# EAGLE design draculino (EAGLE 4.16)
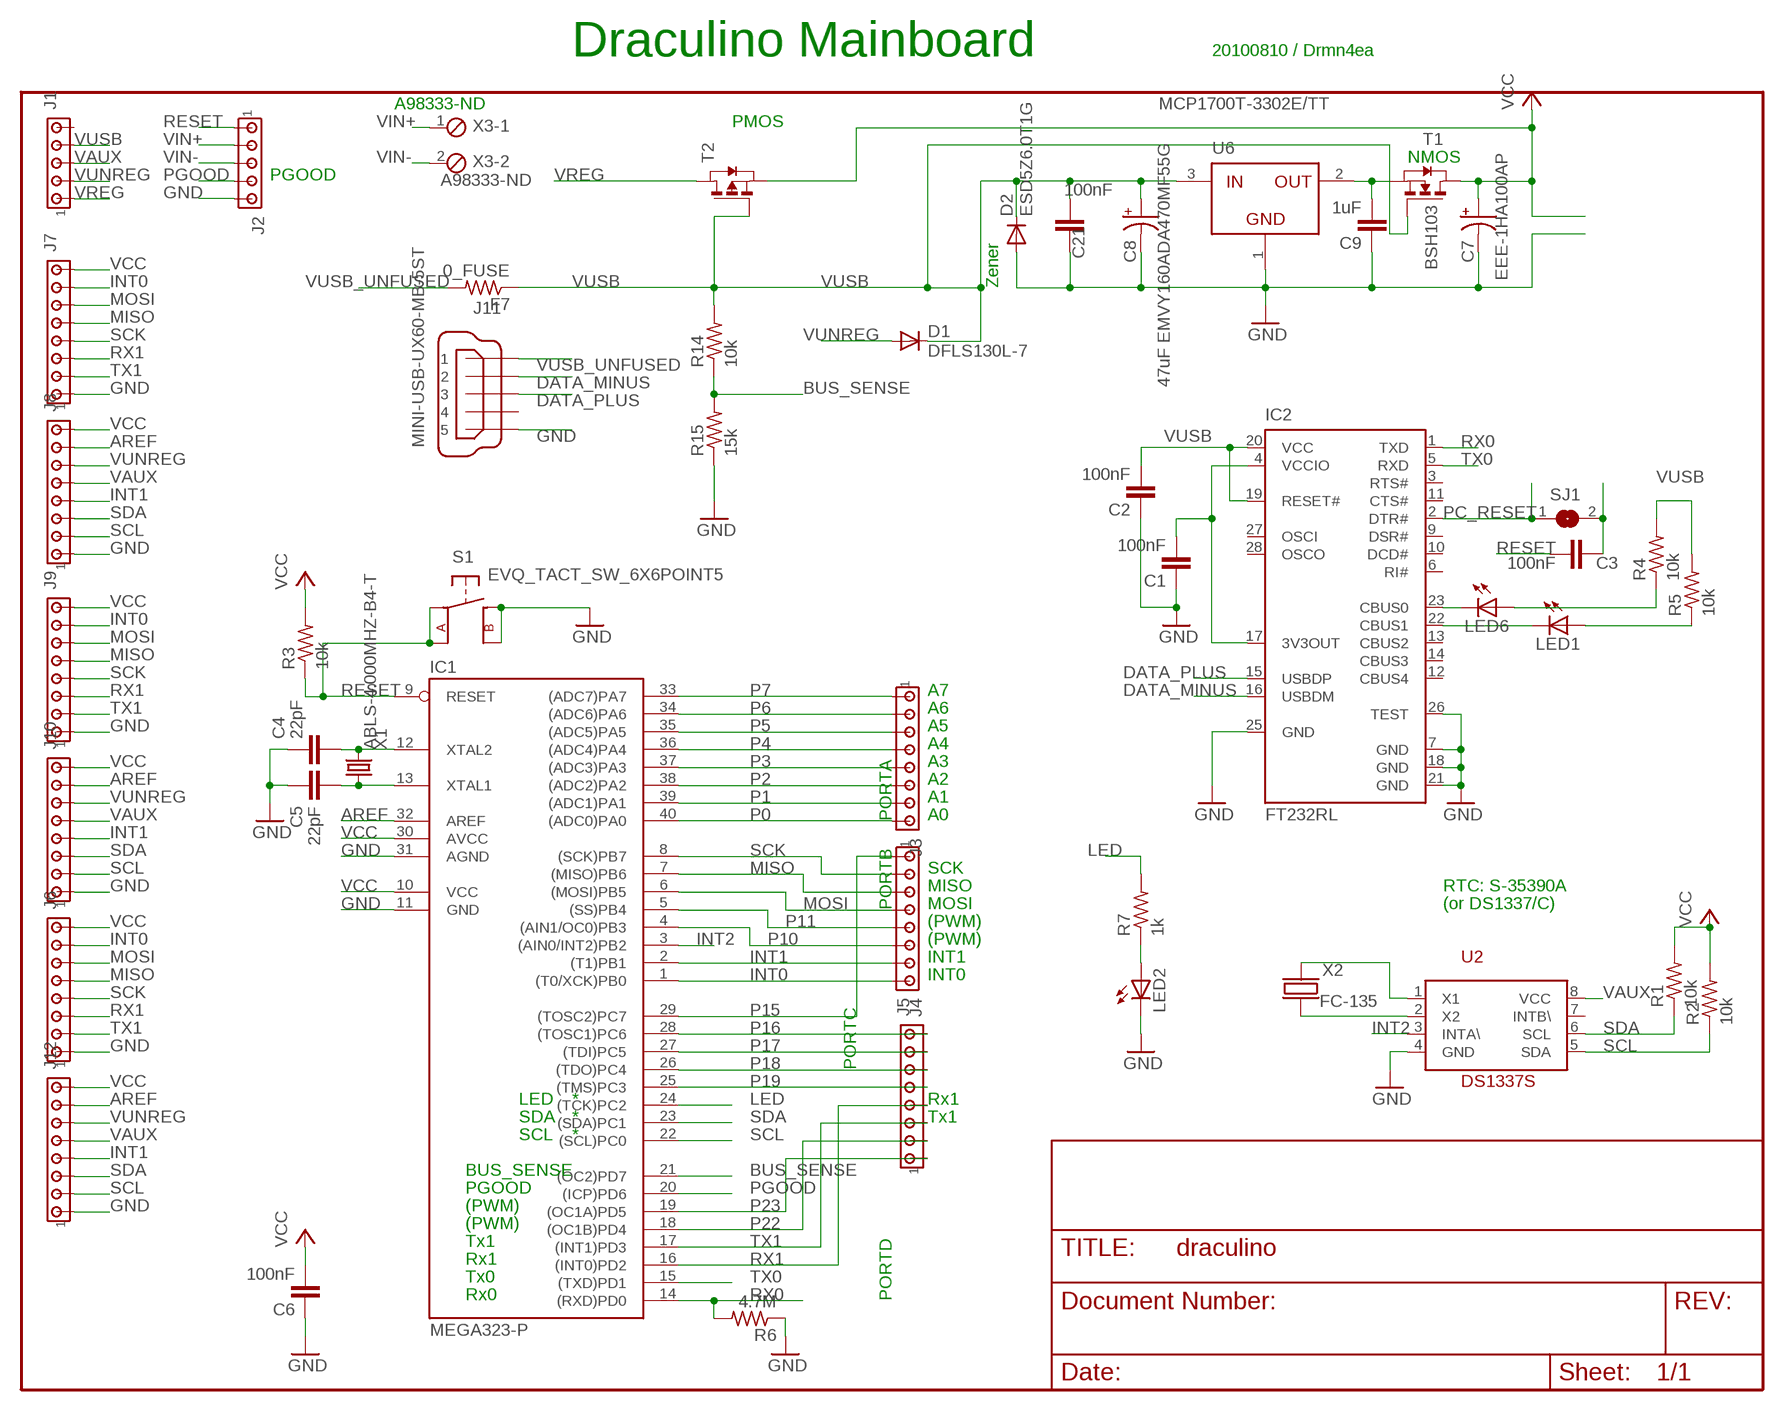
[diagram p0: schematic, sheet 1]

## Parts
C1  100nF  C-EUC0805K  [C0805K]
C2  100nF  C-EUC0805K  [C0805K]
C3  100nF  C-EUC0805K  [C0805K]
C4  22pF  C-EUC0805K  [C0805K]
C5  22pF  C-EUC0805K  [C0805K]
C6  100nF  C-EUC0805K  [C0805K]
C7  EEE-1HA100AP  CPOL-USD  [PANASONIC_D]
C8  47uF EMVY160ADA470MF55G  CPOL-USD  [PANASONIC_D]
C9  1uF  C-EUC0805K  [C0805K]
C21  100nF  C-EUC0805K  [C0805K]
D1  DFLS130L-7  DIODE-SOD123  [SOD123]
D2  ESD5Z6.0T1G  DIODE-SOD123  [SOD123]
F7  0_FUSE  R-US_R0603  [R0603]
IC1  MEGA323-P  [DIL40]
IC2  FT232RL  [SSOP28]
J1  MTA05-100  [10X05MTA]
J2  MTA05-100  [10X05MTA]
J3  MTA08-100  [10X08MTA]
J4  MTA08-100  [10X08MTA]
J5  MTA08-100  [10X08MTA]
J6  MTA08-100  [10X08MTA]
J7  MTA08-100  [10X08MTA]
J8  MTA08-100  [10X08MTA]
J9  MTA08-100  [10X08MTA]
J10  MTA08-100  [10X08MTA]
J11  MINI-USB-UX60-MB-5ST  [UX60-MB-5ST]
J12  MTA08-100  [10X08MTA]
LED1  LEDCHIP-LED0805  [CHIP-LED0805]
LED2  LEDCHIP-LED0805  [CHIP-LED0805]
LED6  LEDCHIP-LED0805  [CHIP-LED0805]
R1  10k  R-US_R0805  [R0805]
R2  10k  R-US_R0805  [R0805]
R3  10k  R-US_R0805  [R0805]
R4  10k  R-US_R0805  [R0805]
R5  10k  R-US_R0805  [R0805]
R6  4.7M  R-US_R0805  [R0805]
R7  1k  R-US_R0805  [R0805]
R14  10k  R-US_R0805  [R0805]
R15  15k  R-US_R0805  [R0805]
S1  EVQ_TACT_SW_6X6POINT5  [EVQ_TACT_SW_6X6POINT5]
SJ1  SJ  [SJ]
T1  BSH103  NMOSSOT23  [SOT-23]
T2  PMOSSOT23  [SOT-23]
U2  DS1337S  [SO-8]
U6  MCP1700T-3302E/TT  MCP1700T  [SOT23]
X1  ABLS-4.000MHZ-B4-T  CRYSTALSM49  [SM49]
X2  FC-135  [FC-135]
X3  A98333-ND  MPT2  [2POL254]

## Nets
AREF: IC1.32(AREF) J8.7 J10.7 J12.7
BUS_SENSE: IC1.21((OC2)PD7) R14.1 R15.2
DATA_MINUS: IC2.16(USBDM) J11.2
DATA_PLUS: IC2.15(USBDP) J11.3
GND: C1.1 C2.1 C4.2 C5.1 C6.1 C7.- C8.- C9.1 C21.1 D2.A IC1.11(GND) IC1.31(AGND) IC2.7(GND) IC2.18(GND) IC2.21(GND) IC2.25(GND) IC2.26(TEST) J2.5 J6.1 J7.1 J8.1 J9.1 J10.1 J11.5 J12.1 LED2.C R6.1 R15.1 S1.B S1.B2(B1) U2.4(GND) U6.1(GND)
INT0: IC1.1((T0/XCK)PB0) J4.8 J6.7 J7.7 J9.7
INT1: IC1.2((T1)PB1) J4.7 J8.4 J10.4 J12.4
INT2: IC1.3((AIN0/INT2)PB2) U2.3(INTA\)
LED: IC1.24((TCK)PC2) R7.2
MISO: IC1.7((MISO)PB6) J4.3 J6.5 J7.5 J9.5
MOSI: IC1.6((MOSI)PB5) J4.4 J6.6 J7.6 J9.6
N$1: C3.1 SJ1.2
N$2: C4.1 IC1.12(XTAL2) X1.2
N$3: LED2.A R7.1
N$4: IC2.22(CBUS1) LED1.C
N$5: C5.2 IC1.13(XTAL1) X1.1
N$6: U2.2(X2) X2.P$2(X2)
N$7: C9.2 T1.2(S) U6.2(OUT)
N$8: U2.1(X1) X2.P$1(X1)
N$9: C1.2 IC2.4(VCCIO) IC2.17(3V3OUT)
N$10: LED6.A R4.1
N$13: IC2.23(CBUS0) LED6.C
N$14: LED1.A R5.1
P0: IC1.40((ADC0)PA0) J3.8
P1: IC1.39((ADC1)PA1) J3.7
P2: IC1.38((ADC2)PA2) J3.6
P3: IC1.37((ADC3)PA3) J3.5
P4: IC1.36((ADC4)PA4) J3.4
P5: IC1.35((ADC5)PA5) J3.3
P6: IC1.34((ADC6)PA6) J3.2
P7: IC1.33((ADC7)PA7) J3.1
P10: IC1.4((AIN1/OC0)PB3) J4.6
P11: IC1.5((SS)PB4) J4.5
P15: IC1.29((TOSC2)PC7) J4.1
P16: IC1.28((TOSC1)PC6) J5.8
P17: IC1.27((TDI)PC5) J5.7
P18: IC1.26((TDO)PC4) J5.6
P19: IC1.25((TMS)PC3) J5.5
P22: IC1.18((OC1B)PD4) J5.2
P23: IC1.19((OC1A)PD5) J5.1
PC_RESET: IC2.2(DTR#) SJ1.1
PGOOD: IC1.20((ICP)PD6) J2.4
RESET: C3.2 IC1.9(RESET) J2.1 R3.1 S1.A S1.A2(A1)
RX0: IC1.14((RXD)PD0) IC2.1(TXD) R6.2
RX1: IC1.16((INT0)PD2) J5.4 J6.3 J7.3 J9.3
SCK: IC1.8((SCK)PB7) J4.2 J6.4 J7.4 J9.4
SCL: IC1.22((SCL)PC0) J8.2 J10.2 J12.2 R2.1 U2.5(SDA)
SDA: IC1.23((SDA)PC1) J8.3 J10.3 J12.3 R1.1 U2.6(SCL)
TX0: IC1.15((TXD)PD1) IC2.5(RXD)
TX1: IC1.17((INT1)PD3) J5.3 J6.2 J7.2 J9.2
VAUX: J1.3 J8.5 J10.5 J12.5 U2.8(VCC)
VCC: C6.2 C7.+ IC1.10(VCC) IC1.30(AVCC) J6.8 J7.8 J8.8 J9.8 J10.8 J12.8 R1.2 R2.2 R3.2 T1.1(D) T2.2(S)
VIN+: J2.2 X3.1
VIN-: J2.3 X3.2
VREG: J1.1 T2.1(D)
VUNREG: D1.A J1.2 J8.6 J10.6 J12.6
VUSB: C2.2 C8.+ C21.2 D1.C D2.C F7.1 IC2.19(RESET#) IC2.20(VCC) J1.4 R4.2 R5.2 R14.2 T1.3(G) T2.3(G) U6.3(IN)
VUSB_UNFUSED: F7.2 J11.1
Unconnected: IC2.3(RTS#) IC2.6(RI#) IC2.9(DSR#) IC2.10(DCD#) IC2.11(CTS#) IC2.12(CBUS4) IC2.13(CBUS2) IC2.14(CBUS3) IC2.27(OSCI) IC2.28(OSCO) J1.5 J11.4 U2.7(INTB\)

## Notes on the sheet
- Draculino Mainboard | 20100810 / Drmn4ea
- A98333-ND
- PMOS
- NMOS
- PGOOD
- Zener
- A7
- A6
- A5
- A4
- A3
- A2
- A1
- PORTA | A0
- SCK
- MISO | RTC: S-35390A
- PORTB | MOSI | (or DS1337/C)
- (PWM)
- (PWM)
- INT1
- INT0
- PORTC
- LED | * | Rx1
- SDA | * | Tx1
- SCL | *
- BUS_SENSE
- PGOOD
- (PWM)
- (PWM)
- Tx1
- Rx1
- Tx0
- Rx0 | PORTD

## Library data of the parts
C1-C6 C9 C21 = rcl:C-EU: CAPACITOR, European symbol
C7 C8 = rcl:CPOL-US: POLARIZED CAPACITOR, American symbol
D1 D2 = diode:DIODE-: DIODE
F7 R1-R7 R14 R15 = rcl:R-US_: RESISTOR, American symbol
IC1 = avr-4:MEGA323-P: MICROCONTROLLER 32 Kbytes FLASH 2 Kbytes SRAM 1 Kbytes EEPROM USART 8-channel 10 bit ADC
IC2 = ftdichip:FT232R: Source: http://www.ftdichip.com/Documents/DataSheets/DS_FT232R_v104.pdf
J1 J2 = con-amp:MTA05-100: AMP connector
J3-J10 J12 = con-amp:MTA08-100: AMP connector
J11 = con-hirose:MINI-USB-: MINI USB Connector Source: http://www.hirose.co.jp/cataloge_hp/e24000019.pdf
LED1 LED2 LED6 = led:LED: LED
S1 = tim:EVQ_TACT_SW_6X6POINT5: Panasonic EVQ series 6.5x6.0mm SMD tactile switch. 20100114 / tgipson
SJ1 = jumper:SJ: SMD solder JUMPER
T1 = zetex:NMOSSOT23: MOS FET
T2 = zetex:PMOSSOT23: MOS FET
U2 = tim:DS1337
U6 = mideeval:MCP1700T: Voltage regulator in SOT23. 20060228 / tgipson
X1 = crystal:CRYSTAL: CRYSTAL
X2 = tim:FC-135
X3 = con-phoenix-254:MPT2: PHOENIX CONNECTOR

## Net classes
1 pwr: width 0.305 mm, drill 0.203 mm, clearance 0.508 mm
4 digital: width 0.203 mm, drill 0.203 mm, clearance 0.381 mm

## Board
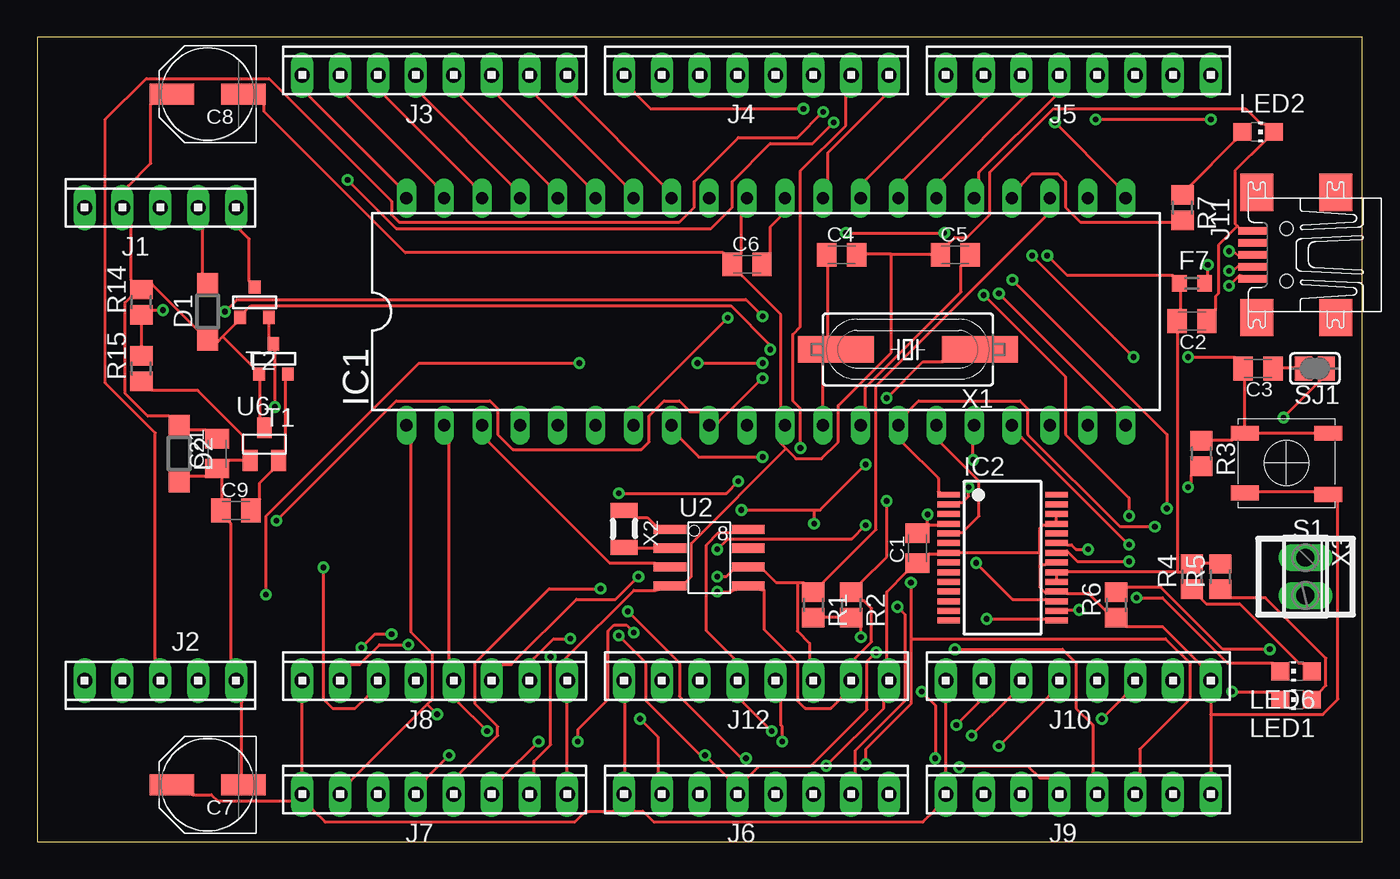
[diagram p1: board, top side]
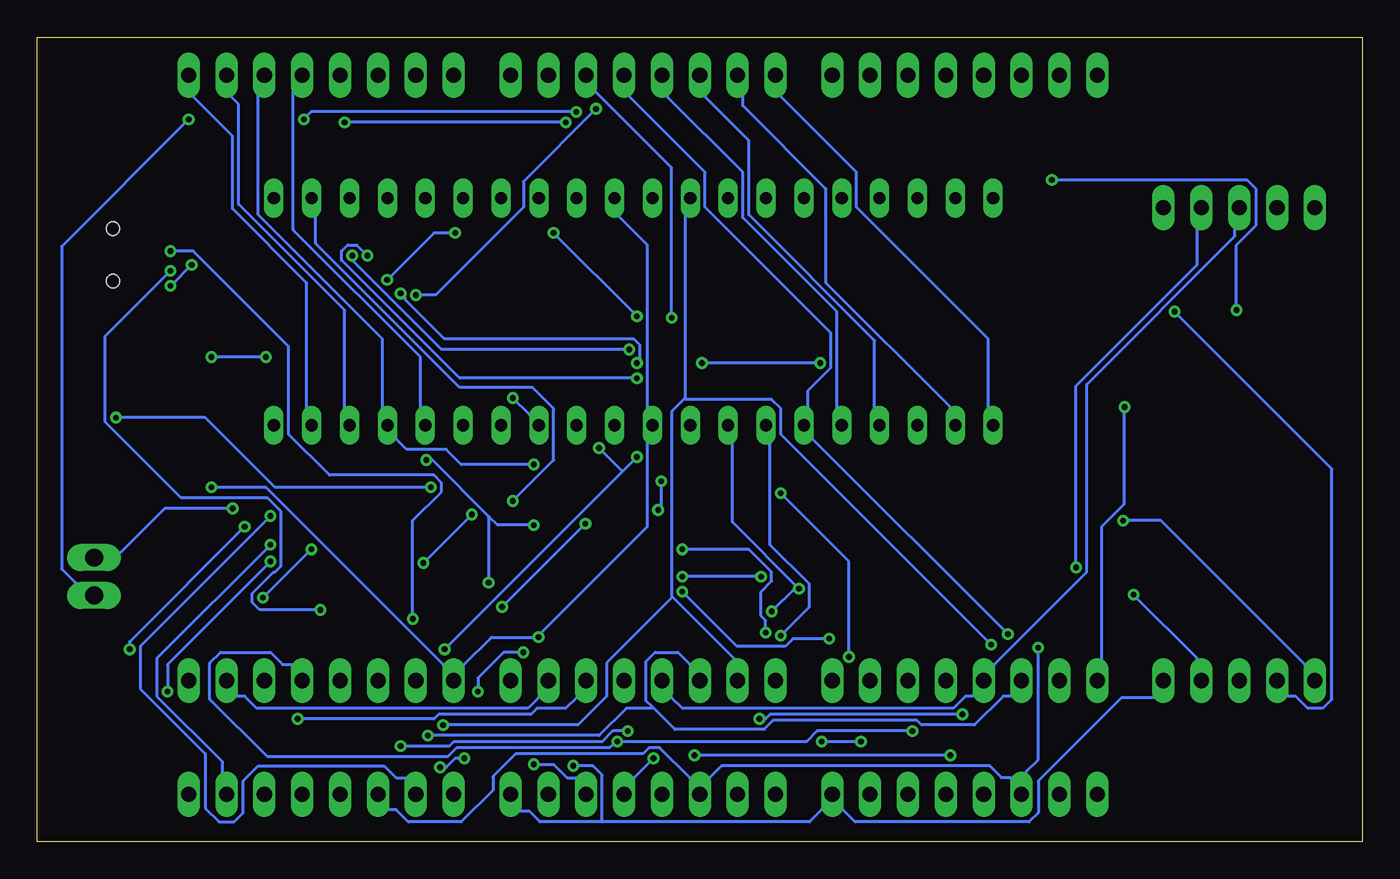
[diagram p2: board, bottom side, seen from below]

Size 88.9 x 53.98 mm. Coordinates in mm from the lower left corner, seen from the top.
Outline: 0,0 88.9,0 88.9,53.98 0,53.98 0,0
Copper layers (1*16): Top 0.035mm / dielectric 1.5mm / Bottom 0.035mm
Design rules "default": minimum track width 8mil, minimum drill 15mil, track to track 8mil, track to pad 8mil, pad to pad 8mil, via to via 8mil, smd to smd 8mil, copper to edge 40mil, drill to drill 8mil, minimum pad ring 10mil, minimum via ring 8mil, stop-mask expansion 4mil, vias tented up to drill 0mil, thermal gap 10mil

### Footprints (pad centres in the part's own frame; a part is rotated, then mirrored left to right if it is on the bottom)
C0805K = smd 1.3 x 1.6: 1 -1,0; 2 1,0
PANASONIC_D = smd 3 x 1.4: + 2.4,0; - -2.4,0
SOD123 = smd 1.4 x 1.4: A 1.9,0; C -1.9,0
R0603 = smd 1 x 1.1: 1 -0.85,0; 2 0.85,0
DIL40 = drill 0.813 long: 1 -24.13,-7.62; 2 -21.59,-7.62; 3 -19.05,-7.62; 4 -16.51,-7.62; 5 -13.97,-7.62; 6 -11.43,-7.62; 7 -8.89,-7.62; 8 -6.35,-7.62; 9 -3.81,-7.62; 10 -1.27,-7.62; 11 1.27,-7.62; 12 3.81,-7.62; 13 6.35,-7.62; 14 8.89,-7.62; 15 11.43,-7.62; 16 13.97,-7.62; 17 16.51,-7.62; 18 19.05,-7.62; 19 21.59,-7.62; 20 24.13,-7.62; 21 24.13,7.62; 22 21.59,7.62; 23 19.05,7.62; 24 16.51,7.62; 25 13.97,7.62; 26 11.43,7.62; 27 8.89,7.62; 28 6.35,7.62; 29 3.81,7.62; 30 1.27,7.62; 31 -1.27,7.62; 32 -3.81,7.62; 33 -6.35,7.62; 34 -8.89,7.62; 35 -11.43,7.62; 36 -13.97,7.62; 37 -16.51,7.62; 38 -19.05,7.62; 39 -21.59,7.62; 40 -24.13,7.62
SSOP28 = smd 0.4 x 1.5: 1 -4.225,-3.625; 2 -3.575,-3.625; 3 -2.925,-3.625; 4 -2.275,-3.625; 5 -1.625,-3.625; 6 -0.975,-3.625; 7 -0.325,-3.625; 8 0.325,-3.625; 9 0.975,-3.625; 10 1.625,-3.625; 11 2.275,-3.625; 12 2.925,-3.625; 13 3.575,-3.625; 14 4.225,-3.625; 15 4.225,3.625; 16 3.575,3.625; 17 2.925,3.625; 18 2.275,3.625; 19 1.625,3.625; 20 0.975,3.625; 21 0.325,3.625; 22 -0.325,3.625; 23 -0.975,3.625; 24 -1.625,3.625; 25 -2.275,3.625; 26 -2.925,3.625; 27 -3.575,3.625; 28 -4.225,3.625
10X05MTA = drill 1.016 long: 1 5.08,0; 2 2.54,0; 3 0,0; 4 -2.54,0; 5 -5.08,0
10X08MTA = drill 1.016 long: 1 8.89,0; 2 6.35,0; 3 3.81,0; 4 1.27,0; 5 -1.27,0; 6 -3.81,0; 7 -6.35,0; 8 -8.89,0
UX60-MB-5ST = smd 2 x 0.5: 1 2.25,1.6; 2 2.25,0.8; 3 2.25,0; 4 2.25,-0.8; 5 2.25,-1.6 | smd 2.2 x 2.5: M1 -3.3,-4.2; M2 -3.3,4.2; M3 2,4.2; M4 2,-4.2 | hole 0.9: 0,-1.75; 0,1.75
CHIP-LED0805 = smd 1.2 x 1.2: A 0,-1.05; C 0,1.05
R0805 = smd 1.3 x 1.5: 1 -0.85,0; 2 0.85,0
EVQ_TACT_SW_6X6POINT5 = smd 1.9 x 1: A -2.8,-2; A2 2.8,-2; B -2.8,2.1; B2 2.8,2
SJ = smd 1.168 x 1.6: 1 -0.762,0; 2 0.762,0
SOT-23 = smd 0.787 x 0.889: 1 0.025,-1.016; 2 -0.94,1.016; 3 0.991,1.016
SO-8 = smd 0.61 x 2.21: 1 -1.905,-2.616; 2 -0.635,-2.616; 3 0.635,-2.616; 4 1.905,-2.616; 5 1.905,2.616; 6 0.635,2.616; 7 -0.635,2.616; 8 -1.905,2.616
SOT23 = smd 1 x 1.4: 1 -0.95,-1.1; 2 0.95,-1.1; 3 0,1.1
SM49 = smd 5.08 x 1.778: 1 -4.826,0; 2 4.826,0
FC-135 = smd 1 x 1.8: P$1 0,0; P$2 2.5,0
2POL254 = drill 1.2 long: 1 -1.27,0; 2 1.27,0

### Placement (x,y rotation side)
C1  59.05,19.68 90 top
C2  77.47,34.92 180 top
C3  81.92,31.75 180 top
C4  53.98,39.37 0 top
C5  61.59,39.37 0 top
C6  47.62,38.73 0 top
C7  11.43,3.81 180 top
C8  11.43,50.16 180 top
C9  13.34,22.23 0 top
C21  12.06,26.04 90 top
D1  11.43,35.56 90 top
D2  9.53,26.04 270 top
F7  77.47,37.47 0 top
IC1  48.9,35.56 0 top
IC2  64.77,19.05 270 top
J1  8.26,42.55 0 top
J2  8.26,10.79 180 top
J3  26.67,51.44 0 top
J4  48.26,51.44 0 top
J5  69.85,51.44 0 top
J6  48.26,3.17 0 top
J7  26.67,3.17 0 top
J8  26.67,10.79 0 top
J9  69.85,3.17 0 top
J10  69.85,10.79 0 top
J11  83.82,39.37 180 top
J12  48.26,10.79 0 top
LED1  84.45,9.53 90 top
LED2  81.92,47.62 270 top
LED6  84.45,11.43 90 top
R1  52.07,15.88 270 top
R2  54.61,15.88 270 top
R3  78.11,26.04 270 top
R4  77.47,17.78 90 top
R5  79.38,17.78 90 top
R6  72.39,15.88 90 top
R7  76.83,42.55 270 top
R14  6.99,36.2 90 top
R15  6.99,31.75 90 top
S1  83.82,25.4 180 top
SJ1  85.72,31.75 180 top
T1  15.88,32.38 180 top
T2  14.61,36.2 180 top
U2  45.09,19.05 270 top
U6  15.24,26.67 0 top
X1  58.42,33.02 180 top
X2  39.37,22.23 270 top
X3  85.09,17.78 270 top

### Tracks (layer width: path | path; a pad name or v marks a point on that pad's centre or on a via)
AREF  (via drill 0.38)
  Top 0.203: v24.89,13.21 22.96,13.21 21.64,11.89 21.03,11.89 J8.7 | v61.67,7.82 63.2,9.35 J10.7
  Bottom 0.203: 45.47,29.72 46.33,28.85 46.33,16.46 46.28,16.41 | 45.47,29.72 45.41,29.77 45.41,41.96 IC1.32 | 46.28,16.41 42.16,12.29 J12.7 | v24.89,13.21 39.01,27.33 39.01,29.06 39.62,29.67 45.41,29.67 45.47,29.72 | v61.67,7.82 52.63,7.82 50.7,9.75 50.7,11.99 46.28,16.41
BUS_SENSE  (via drill 0.38)
  Top 0.203: R15.2 7.01,33.22 7.01,34.75 R14.1 7.72,35.66 v8.43,35.66 | v20.83,44.4 24.08,41.15 45.21,41.15 46.63,42.57 46.63,44.3 49.17,46.84 52.02,46.84 v53.44,48.26 | v68.28,48.26 72.44,44.09 IC1.21
  Bottom 0.203: v8.43,35.66 8.43,40.03 7.11,41.35 7.11,43.79 7.72,44.4 v20.83,44.4 | v53.44,48.26 v68.28,48.26
DATA_MINUS  (via drill 0.38)
  Top 0.203: v69.9,15.54 69.09,15.54 IC2.16 | v79.96,38.3 80.26,38.3 80.67,38.71 J11.2
  Bottom 0.203: v69.9,15.54 73.97,15.54 74.47,16.05 74.47,16.66 73.05,18.09 72.95,18.09 72.54,18.49 72.54,22.15 73.46,23.06 79.25,23.06 84.33,28.14 84.33,33.93 v79.96,38.3
DATA_PLUS  (via drill 0.38)
  Top 0.203: v63.7,14.94 67.67,14.94 IC2.15 | v79.96,39.62 80.26,39.62 80.67,39.22 J11.3
  Bottom 0.203: v63.7,14.94 63.7,21.54 61.77,23.47 61.77,24.08 62.28,24.59 69.29,24.59 72.03,27.33 72.03,33.22 78.44,39.62 v79.96,39.62
GND  (via drill 0.38)
  Top 0.203: 80.52,41.3 80.67,41.15 J11.5 | 80.52,41.3 80.37,41.45 80.37,45.01 82.4,47.04 LED2.C 82.4,48.16 82.09,48.16 81.08,49.17 68.17,49.17 63.91,44.91 63.91,42.06 62.38,40.54 61.57,40.54 61.16,40.13 C5.1 60.05,39.42 57.3,39.42 | C2.1 79.05,35.66 79.05,36.58 79.25,36.78 79.25,40.03 80.52,41.3 | 57.3,39.42 55.58,39.42 C4.2 | C6.1 47.24,39.52 47.24,42.06 IC1.31 | C6.1 47.24,38 49.89,35.36 49.89,29.16 IC1.11 49.89,26.72 50.24,26.36 | C8.- 15.24,49.48 15.24,48.97 24.69,39.52 46.02,39.52 C6.1 | 57.3,39.42 57.3,32.82 53.75,29.26 53.75,26.82 52.63,25.7 50.9,25.7 50.24,26.36 | IC2.26 68.38,21.84 68.38,21.44 IC2.25 67.67,21.23 67.46,21.23 67.26,21.03 67.26,19.41 | 67.31,18.44 67.26,18.39 67.26,17.07 67.67,16.66 IC2.18 69.09,16.66 70.51,16.66 71.73,15.44 R6.1 73.05,14.43 75.49,14.43 78.03,11.89 J10.1 78.74,8.53 | 67.31,18.44 67.46,18.59 67.67,18.59 IC2.21 | 67.26,19.41 67.26,18.49 67.31,18.44 | 67.26,19.41 61.87,19.41 IC2.7 60.45,19.3 59.84,19.3 C1.1 58.32,18.09 57,16.76 57,12.29 J12.1 56.79,9.35 56.79,8.94 v52.93,5.08 | S1.B2 81.89,23.47 85.75,23.47 S1.B 87.27,22.86 87.27,9.55 86.26,8.53 78.74,8.53 | 78.74,8.53 J9.1 | C7.- 13.72,4.47 13.72,9.35 J2.5 13.01,12.29 13.01,21.34 12.9,21.44 C9.1 12.39,22.96 12.39,24.49 C21.1 | D2.A 10.16,24.49 11.28,24.49 C21.1 | C21.1 12.8,25.6 13.82,25.6 U6.1 13.82,26.21 13.82,27.23 10.77,30.28 7.72,30.28 R15.1 | J7.1 J8.1 35.46,12.29 40.03,16.87 41.45,16.87 U2.4 43.48,17.37 43.89,17.78 43.89,20.02 50.24,26.36
  Bottom 0.203: 51,1.32 37.08,1.32 36.27,2.13 J7.1 34.85,2.13 34.04,1.32 22.35,1.32 21.74,1.93 21.74,4.06 16.15,9.65 14.02,9.65 J2.5 | 51,1.32 55.17,1.32 55.88,2.03 56.49,2.03 J6.1 | v52.93,5.08 51.61,5.08 51,4.47 51,1.32
INT0  (via drill 0.38)
  Top 0.203: 26.16,9.2 21.03,4.06 J7.7 | 26.16,9.2 26.52,9.55 26.52,12.6 25.09,14.02 25.09,26.72 IC1.1 | v40.44,8.23 41.66,7.01 41.66,4.67 J6.7 | 26.16,9.2 v26.82,8.53 | v73.25,21.84 73.25,23.06 68.99,27.33 68.99,31.19 v63.5,36.68 | v51.41,49.17 41.15,49.17 40.03,50.29 J4.8
  Bottom 0.203: v40.44,8.23 40.03,8.23 39.73,8.53 v26.82,8.53 | v73.25,21.84 81.99,13.11 81.99,10.26 77.62,5.89 77.62,2.23 76.71,1.32 75.69,1.32 75.08,1.93 75.08,4.06 74.07,5.08 65.63,5.08 64.82,4.27 64.21,4.27 J9.7 | v63.5,36.68 62.18,36.68 56.29,42.57 56.29,44.3 v51.41,49.17 | IC1.1 25.09,29.16 25.09,33.73 33.93,42.57 33.93,44.91 39.01,49.99 J4.8
INT1  (via drill 0.38)
  Top 0.203: IC1.2 27.64,26.72 27.64,12.29 J8.4 28.25,9.35 v30.18,7.42 | v49.99,6.71 49.99,7.72 49.89,7.82 49.89,9.35 J12.4
  Bottom 0.203: J4.7 41.55,49.99 41.55,49.38 35.97,43.79 35.97,37.49 27.64,29.16 IC1.2 | v30.18,7.42 36.58,7.42 37.29,6.71 v49.99,6.71 50.29,6.5 50.49,6.3 60.76,6.3 61.37,5.69 73.46,5.69 77.32,9.55 77.32,11.99 76.61,12.7 73.25,12.7 72.44,11.89 71.83,11.89 J10.4
INT2
  Top 0.203: U2.3 41.45,18.69 38.41,18.69 30.28,26.82 IC1.3
LED
  Top 0.203: R7.2 76.1,41.55 70,41.55 68.99,42.57 68.99,44.3 68.48,44.81 66.75,44.81 66.04,44.09 IC1.24
MISO  (via drill 0.38)
  Top 0.203: v46.33,35.15 40.34,29.16 IC1.7 | v27.64,5.79 26.11,4.27 J7.5 | v61.87,4.98 61.98,5.08 66.45,5.08 67.26,4.27 67.87,4.27 J9.5 | v60.25,5.59 60.25,9.14 v59.33,10.06 | v56.29,12.7 55.68,12.09 55.68,8.84 51.92,5.08 48.46,5.08 47.65,4.27 J6.5 46.33,4.27 v44.81,5.79 44.5,5.79 40.84,9.45 40.84,11.99 v39.01,13.82
  Bottom 0.203: v46.33,35.15 46.33,45.21 51.41,50.29 J4.3 | v27.64,5.79 v44.81,5.79 | v61.87,4.98 61.47,4.98 60.86,5.59 v60.25,5.59 | v59.33,10.06 59.33,10.97 57.61,12.7 v56.29,12.7 | v39.01,13.82 37.08,15.75 37.08,17.27 39.73,19.91 39.73,26.72 IC1.7
MOSI  (via drill 0.38)
  Top 0.203: v23.77,13.92 22.66,13.92 v21.74,13.01
  Bottom 0.203: J4.4 49.17,49.99 44.09,44.91 44.09,42.57 35.66,34.14 35.66,31.8 37.19,30.28 37.19,29.16 IC1.6 36.88,27.03 v23.77,13.92 | J9.6 65.33,2.13 64.82,2.13 64.01,1.32 60.45,1.32 58.32,3.45 58.32,4.37 56.79,5.89 48.26,5.89 47.85,6.3 47.14,6.3 45.11,4.27 J6.6 43.79,4.27 42.98,5.08 24.99,5.08 24.18,4.27 23.57,4.27 J7.6 22.55,4.67 21.74,5.49 v21.74,13.01
N$1
  Top 0.203: C3.1 83.52,31.8 84.43,31.8 SJ1.2
N$2
  Top 0.203: C4.1 53.03,38.61 53.03,33.83 X1.2 52.73,32.21 52.73,29.16 IC1.12
N$3
  Top 0.203: LED2.A 80.37,47.04 77.32,43.99 R7.1
N$4  (via drill 0.38)
  Top 0.203: v80.16,10.06 82.91,10.06 LED1.C | v73.25,18.8 69.8,18.8 69.09,19.51 IC2.22
  Bottom 0.203: v80.16,10.06 80.16,11.89 v73.25,18.8
N$5  (via drill 0.38)
  Top 0.203: C5.2 61.98,38.61 61.98,36.88 55.58,30.48 55.58,29.16 IC1.13 | v57,29.77 59.44,32.21 60.76,32.21 X1.1
  Bottom 0.203: v57,29.77 55.88,28.65 IC1.13
N$6
  Top 0.203: X2.P$2 40.23,19.71 41.45,19.71 U2.2
N$7
  Top 0.203: T1.2 16.66,30.99 16.66,26.21 U6.2 15.75,24.89 14.94,24.08 14.94,22.96 C9.2
N$8
  Top 0.203: X2.P$1 40.23,21.74 40.95,21.74 41.45,21.23 U2.1
N$9  (via drill 0.38)
  Top 0.203: IC2.4 60.45,21.23 59.84,21.23 C1.2 59.74,21.23 v59.74,21.95 | v62.99,18.69 65.43,16.26 67.67,16.26 IC2.17
  Bottom 0.203: v59.74,21.95 v62.99,18.69
N$10
  Top 0.203: LED6.A 84.94,11.99 84.63,11.99 80.67,15.95 78.44,15.95 78.03,16.36 R4.1
N$13  (via drill 0.38)
  Top 0.203: v73.76,16.36 75.49,16.36 79.86,11.99 82.91,11.99 LED6.C | v70.51,19.61 69.7,19.61 69.39,19.91 69.09,19.91 IC2.23
  Bottom 0.203: v70.51,19.61 v73.76,16.36
N$14
  Top 0.203: LED1.A 86.06,10.06 86.46,10.46 86.46,12.29 82.4,16.36 80.06,16.36 R5.1
P0
  Top 0.203: IC1.40 24.18,44.09 18.19,50.09 J3.8
P1
  Top 0.203: IC1.39 26.72,44.09 20.73,50.09 J3.7
P2
  Top 0.203: IC1.38 29.26,44.09 23.27,50.09 J3.6
P3
  Top 0.203: IC1.37 31.8,44.09 25.81,50.09 J3.5
P4
  Top 0.203: IC1.36 34.34,44.09 28.35,50.09 J3.4
P5
  Top 0.203: IC1.35 36.88,44.09 30.89,50.09 J3.3
P6
  Top 0.203: IC1.34 39.42,44.09 33.43,50.09 J3.2
P7
  Top 0.203: IC1.33 41.96,44.09 35.97,50.09 J3.1
P10
  Bottom 0.203: IC1.4 32.72,29.16 32.72,33.63 41.15,42.06 41.15,47.04 44.09,49.99 J4.6
P11
  Bottom 0.203: IC1.5 35.26,29.16 35.26,35.56 41.55,41.86 41.55,44.91 46.63,49.99 J4.5
P15
  Top 0.203: IC1.29 53.03,44.4 53.03,46.23 56.79,49.99 J4.1
P16
  Top 0.203: IC1.28 55.58,44.4 61.16,49.99 J5.8
P17
  Top 0.203: IC1.27 58.12,44.4 63.7,49.99 J5.7
P18
  Top 0.203: IC1.26 60.66,44.4 66.24,49.99 J5.6
P19
  Top 0.203: IC1.25 63.2,44.4 63.2,44.91 68.28,49.99 J5.5
P22
  Bottom 0.203: IC1.18 68.28,29.16 68.28,35.66 75.39,42.77 75.39,49.48 75.89,49.99 J5.2
P23
  Bottom 0.203: IC1.19 70.81,29.16 70.81,37.49 75.79,42.47 75.79,47.35 78.44,49.99 J5.1
PC_RESET  (via drill 0.38)
  Top 0.203: v62.48,23.77 62.48,23.16 62.08,22.76 61.87,22.76 IC2.2 | v83.62,28.45 86.16,30.99 SJ1.1
  Bottom 0.203: v62.48,23.77 72.95,23.77 77.62,28.45 v83.62,28.45
PGOOD  (via drill 0.38)
  Top 0.203: v64.52,36.78 72.44,28.85 IC1.20 | v44.3,32.11 v48.67,32.11 | v36.37,32.11 25.6,32.11 15.34,21.84 v15.34,16.56
  Bottom 0.203: v64.52,36.78 64.21,36.47 64.21,36.37 61.57,33.73 48.87,33.73 48.46,33.33 48.46,32.31 v48.67,32.11 | v36.37,32.11 v44.3,32.11 | v15.34,16.56 11.07,12.29 J2.4
RESET  (via drill 0.38)
  Top 0.203: R3.1 78.84,26.92 80.16,26.92 S1.A2 | S1.A2 80.97,27.84 80.97,30.99 C3.2 80.37,32.51 v77.22,32.51 | S1.A 85.75,27.43 81.89,27.43 S1.A2 | v16.05,21.54 24.08,29.57 30.38,29.57 30.89,29.06 30.89,27.33 31.9,26.31 40.54,26.31 41.05,26.82 41.05,28.55 42.06,29.57 43.08,29.57 43.79,28.85 44.5,28.85 IC1.9 45.72,28.14 v48.67,31.09 | v66.75,39.32 v73.56,32.51
  Bottom 0.203: v16.05,21.54 13.51,21.54 3.86,11.89 J2.1 | v73.56,32.51 v77.22,32.51 | v66.75,39.32 67.46,40.03 68.07,40.03 68.48,39.62 68.48,39.01 60.55,31.09 v48.67,31.09
RX0  (via drill 0.38)
  Top 0.203: IC2.1 60.45,23.47 60.45,24.38 58.12,26.72 IC1.14 58.42,28.85 59.13,29.57 65.94,29.57 66.45,29.06 66.45,27.33 72.64,21.13 v74.98,21.13 | v82.7,12.9 79.55,12.9 75.39,17.07 73.05,17.07 R6.2
  Bottom 0.203: v82.7,12.9 82.7,13.41 v74.98,21.13
RX1  (via drill 0.38)
  Top 0.203: v33.63,6.71 31.19,4.27 J7.3 | v36.27,6.71 36.27,7.52 38.3,9.55 38.3,14.12 38.71,14.53 39.52,14.53 v40.03,14.02 | v45.62,19.61 46.33,20.32 54.66,20.32 v55.58,21.23 | v62.79,25.6 62.79,26.72 IC1.16 | v55.58,5.18 55.58,6.2 58.62,9.25 58.62,13.61 | v58.62,17.37 58.62,13.61 | 58.62,13.61 75.69,13.61 77.32,11.99 77.32,9.55 73.97,6.2 73.97,4.67 J9.3
  Bottom 0.203: IC1.16 63.2,29.16 63.2,32.51 71.73,41.05 71.73,50.29 J5.4 | v33.63,6.71 v36.27,6.71 | v40.03,14.02 40.03,14.83 40.34,15.14 40.34,16.76 39.62,17.48 39.62,18.09 41.15,19.61 v45.62,19.61 | v55.58,21.23 58.01,21.23 58.57,21.79 | 58.57,21.79 62.38,25.6 v62.79,25.6 | v55.58,5.18 54.25,5.18 53.34,4.27 52.73,4.27 J6.3 | v58.62,17.37 58.62,21.74 58.57,21.79
SCK  (via drill 0.38)
  Top 0.203: v37.8,16.97 34.34,16.97 29.36,11.99 29.36,9.25 30.89,7.72 30.89,7.11 28.35,4.57 J7.4 | v47.55,5.59 47.24,5.59 43.08,9.75 43.08,11.99 v39.62,15.44 | v61.57,12.9 68.78,12.9 69.7,11.99 69.7,8.94 70.81,7.82 70.81,4.67 J9.4 | v48.67,25.81 44.4,25.81 43.18,27.03 IC1.8 | v51.21,26.42 51.21,29.06 50.7,29.57 50.7,34.04 51.21,34.54 51.21,45.01 54.25,48.06 54.25,49.99 J4.2
  Bottom 0.203: IC1.8 42.27,26.72 42.27,21.44 v37.8,16.97 38.1,16.97 v39.62,15.44 | v47.55,5.59 48.87,4.27 J6.4 | v48.67,25.81 49.63,24.84 | 49.63,24.84 v61.57,12.9 | 49.63,24.84 v51.21,26.42
SCL  (via drill 0.38)
  Top 0.203: v57,22.86 57,19.1 55.27,17.37 R2.1 55.27,16.15 55.47,16.15 55.98,15.65 55.98,13.41 54.86,12.29 J12.2 53.95,9.65 53.24,8.94 51.51,8.94 51,9.45 51,11.99 48.77,14.22 48.77,16.87 U2.5 46.63,16.87 46.53,16.76 v45.62,16.76 | v35.76,13.61 34.65,13.61 33.33,12.29 J8.2
  Bottom 0.203: v57,22.86 54.25,25.6 54.25,29.06 55.68,30.48 60.55,30.48 70.21,40.13 70.21,41.96 IC1.22 | v35.76,13.61 38.2,13.61 38.71,13.11 41.96,13.11 v45.62,16.76 | J10.2 75.49,9.75 74.98,9.75 74.17,8.94 55.98,8.94 55.27,9.65 J12.2
SDA  (via drill 0.38)
  Top 0.203: 51,17.37 49.58,17.37 48.77,18.19 U2.6 46.63,18.19 46.23,17.78 v45.62,17.78 | 51,17.37 51.41,17.37 R1.1 52.73,17.37 56.29,20.93 56.29,30.58 67.67,41.96 IC1.23 | v40.34,17.78 38.81,16.26 36.17,16.26 31.8,11.89 31.19,11.89 J8.3 | 51,17.37 51,14.12 51.82,13.31 51.82,12.29 J12.3 | v71.42,8.23 72.95,9.75 J10.3
  Bottom 0.203: v40.34,17.78 v45.62,17.78 | v71.42,8.23 62.28,8.23 61.98,8.53 55.78,8.53 55.37,8.94 53.44,8.94 52.73,9.65 J12.3
TX0
  Top 0.203: IC2.5 61.87,20.73 62.08,20.73 63.2,21.84 63.2,24.18 60.66,26.72 IC1.15
TX1  (via drill 0.38)
  Top 0.203: v34.44,12.39 34.44,6.5 33.33,5.38 33.33,4.67 J7.2 | v39.01,23.37 46.23,23.37 v47.04,24.18 | 52.12,22.25 52.53,22.25 v55.58,25.3 | v47.24,22.25 52.12,22.25 | v57.71,15.75 58.22,15.24 58.22,9.45 54.86,6.1 54.86,4.67 J6.2 | 52.12,22.25 v52.12,21.34 | v73.25,19.91 66.04,27.13 IC1.17
  Bottom 0.203: J5.3 74.07,50.09 74.07,42.06 65.73,33.73 65.73,29.16 IC1.17 64.82,27.03 64.11,26.31 61.47,26.31 60.45,25.3 v55.58,25.3 | v34.44,12.39 34.44,18.8 v39.01,23.37 | v47.04,24.18 47.04,22.45 v47.24,22.25 | v52.12,21.34 v57.71,15.75 | v73.25,19.91 80.87,12.29 80.87,9.75 76.5,5.38 76.5,4.67 J9.2
VAUX  (via drill 0.38)
  Top 0.203: U2.8 46.63,20.73 45.72,20.73 44.91,19.91 44.91,14.12 46.74,12.29 J12.5 47.35,9.35 v49.28,7.42 | v64.52,6.4 67.87,9.75 J10.5
  Bottom 0.203: J12.5 46.33,9.65 45.62,8.94 27.43,8.94 26.62,9.75 26.11,9.75 J8.5 24.69,11.89 18.49,18.09 18.49,30.68 8.53,40.64 8.53,41.05 J1.3 | v64.52,6.4 61.27,6.4 60.96,6.71 51,6.71 50.29,7.42 v49.28,7.42
VCC  (via drill 0.38)
  Top 0.203: T2.2 15.54,33.83 T1.1 15.95,33.02 v15.95,29.16 | J6.8 39.42,4.67 39.42,9.35 J12.8 | C7.+ 10.46,3.15 11.68,3.15 12.09,2.74 17.07,2.74 J7.8 | J6.8 38.71,2.03 36.78,2.03 36.07,1.32 19.3,1.32 18.49,2.13 J7.8 | J7.8 J8.8 | C6.2 49.17,39.52 49.17,41.25 49.89,41.96 IC1.30 | R1.2 52.73,15.04 53.95,15.04 R2.2 55.27,14.43 v55.27,13.72 | v77.22,23.77 77.42,23.98 77.42,24.59 R3.2 | J10.8 J9.8 60.25,2.13 59.44,1.32 41.35,1.32 40.64,2.03 40.03,2.03 J6.8
  Bottom 0.203: v15.95,29.16 15.95,22.66 17.48,21.13 17.48,12.29 J8.8 | IC1.30 49.89,41.96 47.95,40.03 47.95,29.16 IC1.10 47.95,26.72 47.95,21.13 55.07,14.02 v55.27,13.72 58.42,13.72 60.25,11.89 J10.8 61.67,11.89 73.56,23.77 v77.22,23.77
VIN+  (via drill 0.38)
  Top 0.203: v12.6,35.56 13.41,36.37 47.55,36.37 v48.67,35.26 | v54.25,40.84 v60.86,40.84 | v65.43,37.69 75.79,27.33 v75.79,22.35
  Bottom 0.203: v12.6,35.56 2.03,24.99 2.03,9.55 2.64,8.94 3.66,8.94 4.47,9.75 4.98,9.75 J2.2 | v48.67,35.26 v54.25,40.84 | v60.86,40.84 62.28,40.84 v65.43,37.69 | v75.79,22.35 80.37,22.35 83.31,19.41 X3.1
VIN-  (via drill 0.38)
  Top 0.203: v52.73,48.97 51,47.24 47.04,47.24 44.09,44.3 44.09,42.57 43.08,41.55 24.28,41.55 23.77,42.06 23.77,42.98 15.54,51.21 7.32,51.21 4.57,48.46 4.57,30.79 7.92,27.43 7.92,12.29 J2.3 | v71.02,48.46 v78.74,48.46
  Bottom 0.203: v52.73,48.97 70.51,48.97 v71.02,48.46 | v78.74,48.46 87.27,39.93 87.27,18.29 86.36,17.37 X3.2
VREG
  Top 0.203: T2.1 14.22,37.59 14.22,40.44 13.61,41.05 J1.1
VUNREG  (via drill 0.38)
  Top 0.203: D1.A 11.07,38.1 11.07,41.05 J1.2 | v62.69,7.11 65.33,9.75 J10.6 | v19.2,18.39 19.2,9.55 19.81,8.94 21.34,8.94 22.15,9.75 J8.6
  Bottom 0.203: 47.6,8.99 48.06,9.45 48.06,12.09 47.45,12.7 45.92,12.7 45.11,11.89 J12.6 | 47.6,8.99 46.13,7.52 40.13,7.52 39.52,8.13 29.87,8.13 29.57,7.82 26.01,7.82 24.08,9.75 23.57,9.75 J8.6 | v62.69,7.11 51.21,7.11 49.38,8.94 47.65,8.94 47.6,8.99 | v19.2,18.39 19.2,30.58 11.07,38.71 11.07,41.05 J1.2
VUSB  (via drill 0.38)
  Top 0.203: IC2.19 68.38,17.58 68.38,17.88 IC2.20 69.09,18.09 76.5,18.09 | R5.2 78.64,18.69 78.13,18.69 R4.2 76.81,18.09 76.5,18.09 | 76.5,18.09 76.5,34.14 C2.2 76.71,35.66 76.71,36.98 F7.1 76.2,38 69.09,38 v67.77,39.32 | 12.45,33.88 12.09,33.53 D1.C 10.77,34.34 7.72,37.39 R14.2 | 12.45,33.88 13.31,34.75 T2.3 13.92,35.56 14.33,35.97 46.53,35.97 49.17,33.33 v49.17,33.02 | U6.3 14.94,28.45 14.94,30.99 T1.3 14.53,31.8 12.45,33.88 | C21.2 11.28,27.64 10.16,27.64 D2.C 8.84,28.55 7.42,28.55 5.89,30.07 5.89,36.17 6.3,36.58 R14.2 | R14.2 6.3,37.69 6.3,41.35 J1.4 6.1,43.99 7.62,45.52 7.62,49.48 C8.+
  Bottom 0.203: v67.77,39.32 67.77,39.01 61.77,33.02 v49.17,33.02
VUSB_UNFUSED  (via drill 0.38)
  Top 0.203: v78.54,38.71 78.54,38 F7.2 | v79.96,37.29 80.67,38 J11.1
  Bottom 0.203: v78.54,38.71 v79.96,37.29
